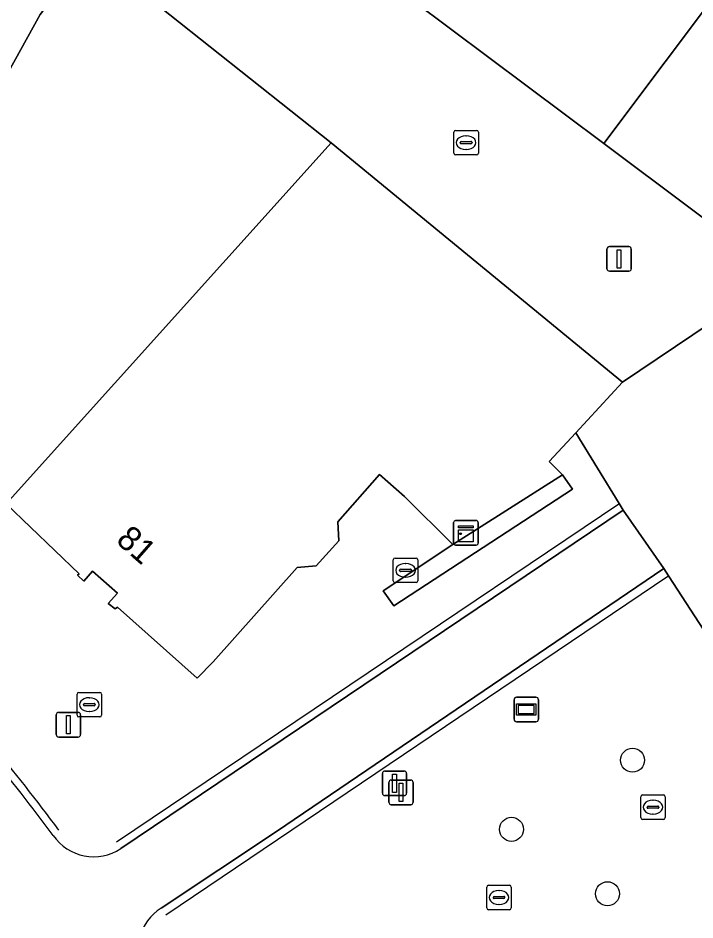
# Model space of a CAD drawing. Extents: x 161087 to 161926, y 382572 to 383873.
# Drawn here: x 161637.83 to 161665.41, y 382995.34 to 383032.06 of the extents above; entities that cross this region are included whole.
import ezdxf

# ---------------------------------------------------------------- set-up
doc = ezdxf.new("R2010")
doc.units = 0
for name, color, linetype in [('IMGEO_Boom', 7, 'Continuous'), ('IMGEO_Erf', 7, 'Continuous'), ('IMGEO_Groenvoorziening', 7, 'Continuous'), ('IMGEO_Kast', 7, 'Continuous'), ('IMGEO_Kolk', 7, 'Continuous'), ('IMGEO_Lichtmast', 7, 'Continuous'), ('IMGEO_Lijnafwatering', 7, 'Continuous'), ('IMGEO_Pand', 7, 'Continuous'), ('IMGEO_Pand_nummerreeks', 7, 'Continuous'), ('IMGEO_Reclamebord', 7, 'Continuous'), ('IMGEO_Rijbaan_lokaal_open', 7, 'Continuous'), ('IMGEO_Voetgangersgebied_gesloten', 7, 'Continuous'), ('IMGEO_Voetgangersgebied_open', 7, 'Continuous')]:
    doc.layers.add(name, color=color, linetype=linetype)

msp = doc.modelspace()

# ---------------------------------------------------------------- linework, layer by layer
at = {"layer": 'IMGEO_Boom'}
for centre in [(161662.868, 383001.84), (161657.937, 382999.025), (161661.846, 382996.403)]:
    msp.add_circle(centre, 0.489, dxfattribs=at)
at = {"layer": 'IMGEO_Erf'}
msp.add_lwpolyline([(161662.454, 383017.231), (161668.892, 383021.561), (161661.701, 383026.943), (161652.326, 383033.961), (161643.003, 383040.94), (161637.551, 383045.021), (161633.754, 383038.504), (161635.817, 383037.41), (161640.737, 383034.802), (161650.586, 383026.982)], close=True, dxfattribs=at)
at = {"layer": 'IMGEO_Groenvoorziening'}
msp.add_lwpolyline([(161660.428, 383012.88), (161660.02, 383013.453), (161655.544, 383010.618), (161652.703, 383008.729), (161653.15, 383008.125)], close=True, dxfattribs=at)
at = {"layer": 'IMGEO_Kast'}
for p, q in [((161655.578, 383010.673), (161655.578, 383011.514)), ((161655.578, 383011.514), (161655.578, 383010.673)), ((161655.653, 383011.598), (161656.494, 383011.598)), ((161656.494, 383011.598), (161655.653, 383011.598)), ((161656.578, 383011.523), (161656.578, 383010.682)), ((161656.578, 383010.682), (161656.578, 383011.523)), ((161656.503, 383010.598), (161655.662, 383010.598)), ((161655.662, 383010.598), (161656.503, 383010.598))]:
    msp.add_line(p, q, dxfattribs=at)
for points in [[(161655.773, 383011.388), (161656.373, 383011.388), (161656.373, 383011.303), (161655.773, 383011.303), (161655.773, 383011.388)], [(161655.773, 383011.213), (161656.373, 383011.213), (161656.373, 383010.724), (161655.773, 383010.724), (161655.773, 383011.213)]]:
    msp.add_lwpolyline(points, dxfattribs=at)
msp.add_circle((161655.857, 383011.062), 0.0377, dxfattribs=at)
for centre, start, end in [((161655.656, 383011.52), 92.4484, 184.2845), ((161655.656, 383011.52), 92.4484, 184.2845), ((161656.5, 383011.52), 2.4484, 94.2845), ((161656.5, 383011.52), 2.4484, 94.2845), ((161655.656, 383010.676), 182.4484, 274.2845), ((161655.656, 383010.676), 182.4484, 274.2845), ((161656.5, 383010.676), 272.4484, 4.2845), ((161656.5, 383010.676), 272.4484, 4.2845)]:
    msp.add_arc(centre, 0.0779, start, end, dxfattribs=at)
at = {"layer": 'IMGEO_Kolk'}
for p, q in [((161655.662, 383027.483), (161656.514, 383027.483)), ((161655.587, 383026.557), (161655.587, 383027.409)), ((161656.075, 383027.263), (161656.1, 383027.263)), ((161656.588, 383027.409), (161656.588, 383026.557)), ((161655.846, 383026.977), (161655.846, 383026.989)), ((161656.284, 383026.94), (161655.886, 383026.94)), ((161655.889, 383027.026), (161656.287, 383027.026)), ((161656.33, 383026.989), (161656.33, 383026.977)), ((161656.514, 383026.483), (161655.662, 383026.483)), ((161656.098, 383026.703), (161656.073, 383026.703)), ((161653.12, 383009.145), (161653.12, 383009.997)), ((161653.195, 383010.071), (161654.047, 383010.071)), ((161653.608, 383009.851), (161653.633, 383009.851)), ((161654.121, 383009.997), (161654.121, 383009.145)), ((161653.379, 383009.565), (161653.379, 383009.577)), ((161653.817, 383009.528), (161653.419, 383009.528)), ((161653.422, 383009.614), (161653.82, 383009.614)), ((161653.863, 383009.577), (161653.863, 383009.565)), ((161653.631, 383009.291), (161653.606, 383009.291)), ((161654.047, 383009.071), (161653.195, 383009.071)), ((161640.239, 383003.676), (161640.239, 383004.528)), ((161640.314, 383004.602), (161641.166, 383004.602)), ((161640.727, 383004.382), (161640.752, 383004.382)), ((161641.24, 383004.528), (161641.24, 383003.676)), ((161640.498, 383004.096), (161640.498, 383004.108)), ((161640.936, 383004.059), (161640.538, 383004.059)), ((161640.541, 383004.145), (161640.939, 383004.145)), ((161640.982, 383004.108), (161640.982, 383004.096)), ((161641.166, 383003.602), (161640.314, 383003.602)), ((161640.75, 383003.822), (161640.725, 383003.822)), ((161663.2, 382999.501), (161663.2, 383000.353)), ((161663.275, 383000.427), (161664.127, 383000.427)), ((161664.201, 383000.353), (161664.201, 382999.501)), ((161663.459, 382999.921), (161663.459, 382999.933)), ((161663.502, 382999.97), (161663.9, 382999.97)), ((161663.688, 383000.207), (161663.713, 383000.207)), ((161663.943, 382999.933), (161663.943, 382999.921)), ((161663.897, 382999.884), (161663.499, 382999.884)), ((161663.711, 382999.647), (161663.686, 382999.647)), ((161664.127, 382999.427), (161663.275, 382999.427)), ((161656.929, 382995.824), (161656.929, 382996.676)), ((161657.004, 382996.75), (161657.856, 382996.75)), ((161657.93, 382996.676), (161657.93, 382995.824)), ((161657.188, 382996.244), (161657.188, 382996.256)), ((161657.231, 382996.293), (161657.629, 382996.293)), ((161657.417, 382996.53), (161657.442, 382996.53)), ((161657.672, 382996.256), (161657.672, 382996.244)), ((161657.626, 382996.207), (161657.228, 382996.207)), ((161657.44, 382995.97), (161657.415, 382995.97)), ((161657.856, 382995.75), (161657.004, 382995.75))]:
    msp.add_line(p, q, dxfattribs=at)
for points in [[(161655.662, 383027.483), (161656.514, 383027.483)], [(161655.587, 383026.557), (161655.587, 383027.409)], [(161656.588, 383027.409), (161656.588, 383026.557)], [(161656.514, 383026.483), (161655.662, 383026.483)], [(161653.12, 383009.145), (161653.12, 383009.997)], [(161653.195, 383010.071), (161654.047, 383010.071)], [(161654.121, 383009.997), (161654.121, 383009.145)], [(161654.047, 383009.071), (161653.195, 383009.071)], [(161640.239, 383003.676), (161640.239, 383004.528)], [(161640.314, 383004.602), (161641.166, 383004.602)], [(161641.24, 383004.528), (161641.24, 383003.676)], [(161641.166, 383003.602), (161640.314, 383003.602)], [(161663.2, 382999.501), (161663.2, 383000.353)], [(161663.275, 383000.427), (161664.127, 383000.427)], [(161664.201, 383000.353), (161664.201, 382999.501)], [(161664.127, 382999.427), (161663.275, 382999.427)], [(161656.929, 382995.824), (161656.929, 382996.676)], [(161657.004, 382996.75), (161657.856, 382996.75)], [(161657.93, 382996.676), (161657.93, 382995.824)], [(161657.856, 382995.75), (161657.004, 382995.75)]]:
    msp.add_lwpolyline(points, dxfattribs=at)
for centre, radius, start, end in [((161655.664, 383027.407), 0.0765, 91.552, 178.448), ((161655.664, 383027.407), 0.0765, 91.552, 178.448), ((161656.512, 383027.407), 0.0765, 1.552, 88.448), ((161656.512, 383027.407), 0.0765, 1.552, 88.448), ((161655.886, 383026.986), 0.0403, 85.8775, 175.7526), ((161655.883, 383026.976), 0.0366, 178.938, 274.7102), ((161656.287, 383026.983), 0.043, 264.8664, 352.4533), ((161656.291, 383026.988), 0.0386, 1.7309, 96.639), ((161655.664, 383026.559), 0.0765, 181.552, 268.448), ((161655.664, 383026.559), 0.0765, 181.552, 268.448), ((161656.512, 383026.559), 0.0765, 271.552, 358.448), ((161656.512, 383026.559), 0.0765, 271.552, 358.448), ((161653.197, 383009.995), 0.0765, 91.552, 178.448), ((161653.197, 383009.995), 0.0765, 91.552, 178.448), ((161654.045, 383009.995), 0.0765, 1.552, 88.448), ((161654.045, 383009.995), 0.0765, 1.552, 88.448), ((161653.419, 383009.574), 0.0403, 85.8775, 175.7526), ((161653.416, 383009.564), 0.0366, 178.938, 274.7102), ((161653.82, 383009.571), 0.043, 264.8664, 352.4533), ((161653.824, 383009.576), 0.0386, 1.7309, 96.639), ((161653.197, 383009.147), 0.0765, 181.552, 268.448), ((161653.197, 383009.147), 0.0765, 181.552, 268.448), ((161654.045, 383009.147), 0.0765, 271.552, 358.448), ((161654.045, 383009.147), 0.0765, 271.552, 358.448), ((161640.316, 383004.526), 0.0765, 91.552, 178.448), ((161640.316, 383004.526), 0.0765, 91.552, 178.448), ((161641.164, 383004.526), 0.0765, 1.552, 88.448), ((161641.164, 383004.526), 0.0765, 1.552, 88.448), ((161640.538, 383004.105), 0.0403, 85.8775, 175.7526), ((161640.535, 383004.095), 0.0366, 178.938, 274.7102), ((161640.939, 383004.102), 0.043, 264.8664, 352.4533), ((161640.943, 383004.107), 0.0386, 1.7309, 96.639), ((161640.316, 383003.678), 0.0765, 181.552, 268.448), ((161640.316, 383003.678), 0.0765, 181.552, 268.448), ((161641.164, 383003.678), 0.0765, 271.552, 358.448), ((161641.164, 383003.678), 0.0765, 271.552, 358.448), ((161663.277, 383000.351), 0.0765, 91.552, 178.448), ((161663.277, 383000.351), 0.0765, 91.552, 178.448), ((161664.125, 383000.351), 0.0765, 1.552, 88.448), ((161664.125, 383000.351), 0.0765, 1.552, 88.448), ((161663.499, 382999.93), 0.0403, 85.8775, 175.7526), ((161663.496, 382999.92), 0.0366, 178.938, 274.7102), ((161663.9, 382999.927), 0.043, 264.8664, 352.4533), ((161663.904, 382999.932), 0.0386, 1.7309, 96.639), ((161663.277, 382999.503), 0.0765, 181.552, 268.448), ((161663.277, 382999.503), 0.0765, 181.552, 268.448), ((161664.125, 382999.503), 0.0765, 271.552, 358.448), ((161664.125, 382999.503), 0.0765, 271.552, 358.448), ((161657.006, 382996.674), 0.0765, 91.552, 178.448), ((161657.006, 382996.674), 0.0765, 91.552, 178.448), ((161657.854, 382996.674), 0.0765, 1.552, 88.448), ((161657.854, 382996.674), 0.0765, 1.552, 88.448), ((161657.228, 382996.253), 0.0403, 85.8775, 175.7526), ((161657.225, 382996.243), 0.0366, 178.938, 274.7102), ((161657.629, 382996.25), 0.043, 264.8664, 352.4533), ((161657.633, 382996.255), 0.0386, 1.7309, 96.639), ((161657.006, 382995.826), 0.0765, 181.552, 268.448), ((161657.006, 382995.826), 0.0765, 181.552, 268.448), ((161657.854, 382995.826), 0.0765, 271.552, 358.448), ((161657.854, 382995.826), 0.0765, 271.552, 358.448)]:
    msp.add_arc(centre, radius, start, end, dxfattribs=at)
for centre, major_axis, ratio, start_param, end_param in [((161656.074, 383026.983), (-0.387, 0.002), 0.722429, 4.712389, 7.853982), ((161656.099, 383026.983), (-0.39, 0.002), 0.717154, 1.570796, 4.712389), ((161653.607, 383009.571), (-0.387, 0.002), 0.722429, 4.712389, 7.853982), ((161653.632, 383009.571), (-0.39, 0.002), 0.717154, 1.570796, 4.712389), ((161640.726, 383004.102), (-0.387, 0.002), 0.722429, 4.712389, 7.853982), ((161640.751, 383004.102), (-0.39, 0.002), 0.717154, 1.570796, 4.712389), ((161663.687, 382999.927), (-0.387, 0.002), 0.722429, 4.712389, 7.853982), ((161663.712, 382999.927), (-0.39, 0.002), 0.717154, 1.570796, 4.712389), ((161657.416, 382996.25), (-0.387, 0.002), 0.722429, 4.712389, 7.853982), ((161657.441, 382996.25), (-0.39, 0.002), 0.717154, 1.570796, 4.712389)]:
    msp.add_ellipse(centre, major_axis=major_axis, ratio=ratio, start_param=start_param, end_param=end_param, dxfattribs=at)
at = {"layer": 'IMGEO_Lichtmast'}
for p, q in [((161661.928, 383022.75), (161662.718, 383022.75)), ((161662.718, 383022.75), (161661.928, 383022.75)), ((161661.828, 383021.85), (161661.828, 383022.65)), ((161661.828, 383022.65), (161661.828, 383021.85)), ((161662.818, 383022.65), (161662.818, 383021.85)), ((161662.818, 383021.85), (161662.818, 383022.65)), ((161662.718, 383021.75), (161661.928, 383021.75)), ((161661.928, 383021.75), (161662.718, 383021.75)), ((161639.39, 383002.884), (161639.39, 383003.684)), ((161639.39, 383003.684), (161639.39, 383002.884)), ((161639.49, 383003.784), (161640.28, 383003.784)), ((161640.28, 383003.784), (161639.49, 383003.784)), ((161640.38, 383003.684), (161640.38, 383002.884)), ((161640.38, 383002.884), (161640.38, 383003.684)), ((161640.28, 383002.784), (161639.49, 383002.784)), ((161639.49, 383002.784), (161640.28, 383002.784)), ((161652.776, 383001.399), (161653.566, 383001.399)), ((161653.566, 383001.399), (161652.776, 383001.399)), ((161652.676, 383000.499), (161652.676, 383001.299)), ((161652.676, 383001.299), (161652.676, 383000.499)), ((161653.04, 383001.029), (161653.83, 383001.029)), ((161653.83, 383001.029), (161653.04, 383001.029)), ((161653.666, 383001.299), (161653.666, 383000.499)), ((161653.666, 383000.499), (161653.666, 383001.299)), ((161652.94, 383000.129), (161652.94, 383000.929)), ((161652.94, 383000.929), (161652.94, 383000.129)), ((161653.93, 383000.929), (161653.93, 383000.129)), ((161653.93, 383000.129), (161653.93, 383000.929)), ((161653.566, 383000.399), (161652.776, 383000.399)), ((161652.776, 383000.399), (161653.566, 383000.399)), ((161653.83, 383000.029), (161653.04, 383000.029)), ((161653.04, 383000.029), (161653.83, 383000.029))]:
    msp.add_line(p, q, dxfattribs=at)
for points in [[(161662.248, 383022.625), (161662.398, 383022.625), (161662.398, 383021.875), (161662.248, 383021.875), (161662.248, 383022.625)], [(161639.81, 383003.659), (161639.96, 383003.659), (161639.96, 383002.909), (161639.81, 383002.909), (161639.81, 383003.659)], [(161653.096, 383001.274), (161653.246, 383001.274), (161653.246, 383000.524), (161653.096, 383000.524), (161653.096, 383001.274)], [(161653.36, 383000.904), (161653.51, 383000.904), (161653.51, 383000.154), (161653.36, 383000.154), (161653.36, 383000.904)]]:
    msp.add_lwpolyline(points, dxfattribs=at)
for centre, start, end in [((161661.928, 383022.65), 90, 180), ((161661.928, 383022.65), 90, 180), ((161662.718, 383022.65), 0, 90), ((161662.718, 383022.65), 360, 90), ((161661.928, 383021.85), 180, 270), ((161661.928, 383021.85), 180, 270), ((161662.718, 383021.85), 270, 0), ((161662.718, 383021.85), 270, 0), ((161639.49, 383003.684), 90, 180), ((161639.49, 383003.684), 90, 180), ((161640.28, 383003.684), 0, 90), ((161640.28, 383003.684), 360, 90), ((161639.49, 383002.884), 180, 270), ((161639.49, 383002.884), 180, 270), ((161640.28, 383002.884), 270, 0), ((161640.28, 383002.884), 270, 0), ((161652.776, 383001.299), 90, 180), ((161652.776, 383001.299), 90, 180), ((161653.566, 383001.299), 0, 90), ((161653.566, 383001.299), 360, 90), ((161653.04, 383000.929), 90, 180), ((161653.04, 383000.929), 90, 180), ((161653.83, 383000.929), 0, 90), ((161653.83, 383000.929), 360, 90), ((161652.776, 383000.499), 180, 270), ((161652.776, 383000.499), 180, 270), ((161653.566, 383000.499), 270, 0), ((161653.566, 383000.499), 270, 0), ((161653.04, 383000.129), 180, 270), ((161653.04, 383000.129), 180, 270), ((161653.83, 383000.129), 270, 0), ((161653.83, 383000.129), 270, 0)]:
    msp.add_arc(centre, 0.1, start, end, dxfattribs=at)
at = {"layer": 'IMGEO_Lijnafwatering'}
for points in [[(161641.85, 382998.522), (161662.345, 383012.299)], [(161643.848, 382995.547), (161664.342, 383009.361)]]:
    msp.add_lwpolyline(points, dxfattribs=at)
msp.add_arc((161571.231, 382948.219), 85.079, 36.64081, 42.69607, dxfattribs=at)
at = {"layer": 'IMGEO_Pand'}
for points in [[(161663.576, 383036.225), (161662.804, 383035.298), (161659.278, 383038.256), (161656.982, 383040.181), (161652.326, 383033.961), (161661.701, 383026.943), (161666.691, 383033.608), (161665.177, 383034.88)], [(161638.738, 383032.194), (161640.737, 383034.802), (161635.817, 383037.41), (161633.754, 383038.504), (161633.206, 383038.687), (161630.584, 383033.897), (161629.987, 383034.224), (161622.995, 383020.312), (161625.424, 383019.068), (161625.395, 383019.012), (161626.028, 383018.684), (161626.051, 383018.728), (161627.1, 383018.21), (161627.079, 383018.166), (161630.716, 383016.23), (161630.721, 383016.28), (161630.82, 383016.229), (161635.821, 383026.367), (161635.573, 383026.502)], [(161650.586, 383026.982), (161640.737, 383034.802), (161638.738, 383032.194), (161635.573, 383026.502), (161635.821, 383026.367), (161630.82, 383016.229), (161632.857, 383015.192), (161632.905, 383015.281), (161633.451, 383014.988), (161633.431, 383014.957), (161634.582, 383014.346), (161634.604, 383014.423), (161635.168, 383014.151), (161637.333, 383012.295), (161637.344, 383012.284)], [(161669.033, 383030.073), (161669.805, 383030.992), (161667.284, 383033.11), (161666.691, 383033.608), (161661.701, 383026.943), (161668.892, 383021.561), (161674.604, 383025.405), (161673.51, 383026.327)], [(161652.566, 383013.472), (161653.573, 383012.57), (161655.544, 383010.618), (161660.02, 383013.453), (161659.478, 383014.001), (161660.559, 383015.174), (161662.454, 383017.231), (161650.586, 383026.982), (161637.344, 383012.284), (161640.329, 383009.433), (161640.254, 383009.369), (161640.52, 383009.135), (161640.87, 383009.533), (161641.884, 383008.642), (161641.505, 383008.226), (161641.789, 383008), (161641.889, 383008.073), (161645.131, 383005.176), (161645.784, 383005.848), (161649.211, 383009.688), (161649.986, 383009.76), (161650.897, 383010.766), (161650.857, 383011.543)]]:
    msp.add_lwpolyline(points, close=True, dxfattribs=at)
at = {"layer": 'IMGEO_Reclamebord'}
for p, q in [((161658.143, 383004.404), (161658.933, 383004.404)), ((161658.933, 383004.404), (161658.143, 383004.404)), ((161658.043, 383003.504), (161658.043, 383004.304)), ((161658.043, 383004.304), (161658.043, 383003.504)), ((161659.033, 383004.304), (161659.033, 383003.504)), ((161659.033, 383003.504), (161659.033, 383004.304)), ((161658.933, 383003.404), (161658.143, 383003.404)), ((161658.143, 383003.404), (161658.933, 383003.404))]:
    msp.add_line(p, q, dxfattribs=at)
for points in [[(161658.144, 383004.136), (161658.932, 383004.136), (161658.932, 383003.672), (161658.144, 383003.672), (161658.144, 383004.136)], [(161658.209, 383004.071), (161658.209, 383003.737), (161658.867, 383003.737), (161658.867, 383004.071), (161658.209, 383004.071)]]:
    msp.add_lwpolyline(points, dxfattribs=at)
for centre, start, end in [((161658.143, 383004.304), 90, 180), ((161658.143, 383004.304), 90, 180), ((161658.933, 383004.304), 0, 90), ((161658.933, 383004.304), 360, 90), ((161658.143, 383003.504), 180, 270), ((161658.143, 383003.504), 180, 270), ((161658.933, 383003.504), 270, 0), ((161658.933, 383003.504), 270, 0)]:
    msp.add_arc(centre, 0.1, start, end, dxfattribs=at)
at = {"layer": 'IMGEO_Rijbaan_lokaal_open'}
msp.add_lwpolyline([(161668.892, 383021.561), (161662.454, 383017.231), (161660.559, 383015.174), (161662.32, 383012.295), (161662.492, 383012.013), (161664.14, 383009.646), (161664.334, 383009.348), (161666.657, 383005.779)], dxfattribs=at)
at = {"layer": 'IMGEO_Voetgangersgebied_gesloten'}
msp.add_lwpolyline([(161643.67, 382995.817), (161648.36, 382998.939), (161664.14, 383009.646), (161662.492, 383012.013), (161642.024, 382998.245)], dxfattribs=at)
for centre, radius, start, end in [((161577.584, 382953.191), 76.699, 36.46871, 42.90917), ((161640.914, 382999.904), 1.996, 214.2606, 303.799), ((161644.686, 382994.149), 1.953, 121.3499, 209.7305)]:
    msp.add_arc(centre, radius, start, end, dxfattribs=at)
at = {"layer": 'IMGEO_Voetgangersgebied_open'}
for points in [[(161642.024, 382998.245), (161662.492, 383012.013), (161662.32, 383012.295), (161660.559, 383015.174), (161659.478, 383014.001), (161660.02, 383013.453), (161660.428, 383012.88), (161653.15, 383008.125), (161652.703, 383008.729), (161655.544, 383010.618), (161653.573, 383012.57), (161652.566, 383013.472), (161650.857, 383011.543), (161650.897, 383010.766), (161649.986, 383009.76), (161649.211, 383009.688), (161645.784, 383005.848), (161645.131, 383005.176), (161641.889, 383008.073), (161641.789, 383008), (161641.505, 383008.226), (161641.884, 383008.642), (161640.87, 383009.533), (161640.52, 383009.135), (161640.254, 383009.369), (161640.329, 383009.433), (161637.344, 383012.284)], [(161672.003, 382997.08), (161670.999, 382998.574), (161670.04, 383000), (161666.311, 383005.546), (161666.657, 383005.779), (161664.334, 383009.348), (161664.14, 383009.646), (161648.36, 382998.939), (161643.67, 382995.817)]]:
    msp.add_lwpolyline(points, dxfattribs=at)
for centre, radius, start, end in [((161577.584, 382953.191), 76.699, 36.46871, 42.90917), ((161640.914, 382999.904), 1.996, 214.2606, 303.799), ((161644.686, 382994.149), 1.953, 121.3499, 209.7305)]:
    msp.add_arc(centre, radius, start, end, dxfattribs=at)

# ---------------------------------------------------------------- texts
at = {"layer": 'IMGEO_Pand_nummerreeks'}
msp.add_text('81', height=1, rotation=318.6955, dxfattribs=at).set_placement((161641.778, 383010.731))

doc.saveas('drawing.dxf')
